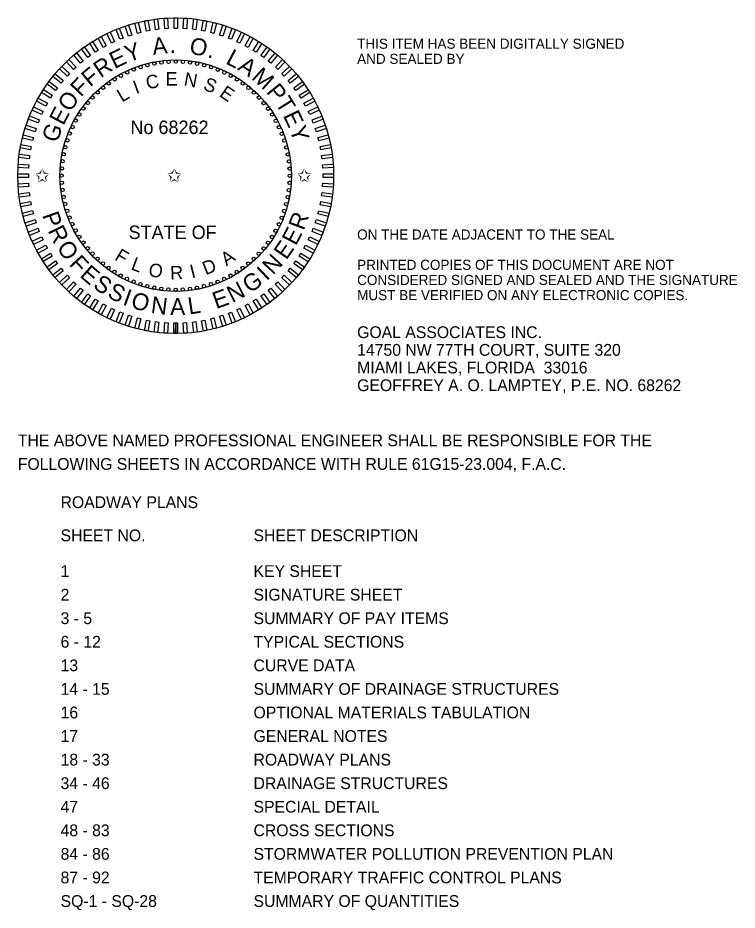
# Model space of a CAD drawing. Extents: x -811 to -790, y -2284 to -2178.
# Drawn here: x -810.41 to -806.14, y -2184.26 to -2178.96 of the extents above; entities that cross this region are included whole.
import ezdxf

# ---------------------------------------------------------------- set-up
doc = ezdxf.new("R2010")
doc.units = 0
for name, color, linetype in [('PlotBorder_dp', 7, 'Continuous'), ('TextMinor', 7, 'Continuous'), ('TextMisc', 7, 'Continuous'), ('TextShtNo', 7, 'Continuous')]:
    doc.layers.add(name, color=color, linetype=linetype)

msp = doc.modelspace()

# ---------------------------------------------------------------- linework, layer by layer
at = {"layer": 'TextMinor'}
for radius in [0.9375, 0.6875]:
    msp.add_circle((-809.477, -2179.9009), radius, dxfattribs=at)
at = {"layer": 'TextShtNo'}
for p, q in [((-809.487, -2180.8384), (-809.4871, -2180.7759)), ((-809.477, -2180.8384), (-809.4771, -2180.7759)), ((-809.467, -2180.8383), (-809.4671, -2180.7758))]:
    msp.add_line(p, q, dxfattribs=at)
for points in [[(-809.6309, -2179.0394), (-809.6507, -2179.0432), (-809.6624, -2178.9819), (-809.6426, -2178.9781)], [(-809.5765, -2179.0315), (-809.5965, -2179.034), (-809.6044, -2178.972), (-809.5843, -2178.9695)], [(-809.5217, -2179.0269), (-809.5419, -2179.0282), (-809.5458, -2178.9659), (-809.5256, -2178.9646)], [(-809.4668, -2179.0258), (-809.487, -2179.0258), (-809.487, -2178.9634), (-809.4668, -2178.9634)], [(-809.4118, -2179.0282), (-809.432, -2179.0269), (-809.4281, -2178.9646), (-809.4079, -2178.9659)], [(-809.3572, -2179.034), (-809.3772, -2179.0315), (-809.3694, -2178.9695), (-809.3493, -2178.9721)], [(-809.303, -2179.0432), (-809.3228, -2179.0395), (-809.3111, -2178.9781), (-809.2913, -2178.9819)], [(-809.7896, -2179.0835), (-809.8084, -2179.091), (-809.8314, -2179.0329), (-809.8126, -2179.0255)], [(-809.7377, -2179.0655), (-809.7569, -2179.0718), (-809.7762, -2179.0124), (-809.757, -2179.0061)], [(-809.6847, -2179.0508), (-809.7042, -2179.0558), (-809.7198, -2178.9953), (-809.7002, -2178.9903)], [(-809.2495, -2179.0559), (-809.269, -2179.0508), (-809.2535, -2178.9904), (-809.2339, -2178.9954)], [(-809.1969, -2179.0718), (-809.2161, -2179.0656), (-809.1968, -2179.0062), (-809.1776, -2179.0124)], [(-809.1454, -2179.091), (-809.1641, -2179.0836), (-809.1411, -2179.0256), (-809.1224, -2179.033)], [(-809.8896, -2179.1292), (-809.9073, -2179.1389), (-809.9373, -2179.0842), (-809.9197, -2179.0745)], [(-809.8403, -2179.1048), (-809.8586, -2179.1134), (-809.8852, -2179.0569), (-809.8669, -2179.0483)], [(-809.0952, -2179.1135), (-809.1134, -2179.1049), (-809.0868, -2179.0484), (-809.0686, -2179.057)], [(-809.0465, -2179.139), (-809.0642, -2179.1293), (-809.0341, -2179.0745), (-809.0164, -2179.0843)], [(-809.983, -2179.187), (-809.9994, -2179.1988), (-810.0361, -2179.1483), (-810.0197, -2179.1365)], [(-809.9372, -2179.1566), (-809.9543, -2179.1674), (-809.9877, -2179.1147), (-809.9707, -2179.1039)], [(-808.9995, -2179.1675), (-809.0165, -2179.1567), (-808.9831, -2179.104), (-808.966, -2179.1148)], [(-808.9544, -2179.1989), (-808.9707, -2179.1871), (-808.934, -2179.1366), (-808.9177, -2179.1484)], [(-810.0269, -2179.2202), (-810.0424, -2179.233), (-810.0822, -2179.1849), (-810.0667, -2179.172)], [(-808.9113, -2179.2331), (-808.9269, -2179.2203), (-808.8871, -2179.1722), (-808.8715, -2179.185)], [(-810.0685, -2179.256), (-810.0832, -2179.2698), (-810.126, -2179.2243), (-810.1113, -2179.2105)], [(-808.8705, -2179.27), (-808.8852, -2179.2562), (-808.8425, -2179.2106), (-808.8278, -2179.2245)], [(-810.1447, -2179.3353), (-810.1575, -2179.3508), (-810.2057, -2179.311), (-810.1928, -2179.2955)], [(-810.1078, -2179.2944), (-810.1217, -2179.3092), (-810.1672, -2179.2664), (-810.1534, -2179.2517)], [(-808.8321, -2179.3093), (-808.8459, -2179.2946), (-808.8004, -2179.2518), (-808.7866, -2179.2666)], [(-808.7962, -2179.351), (-808.8091, -2179.3354), (-808.761, -2179.2956), (-808.7481, -2179.3112)], [(-810.1789, -2179.3783), (-810.1907, -2179.3946), (-810.2413, -2179.3579), (-810.2294, -2179.3416)], [(-808.763, -2179.3948), (-808.7749, -2179.3784), (-808.7244, -2179.3417), (-808.7125, -2179.3581)], [(-810.2103, -2179.4234), (-810.2211, -2179.4404), (-810.2738, -2179.407), (-810.263, -2179.3899)], [(-808.7327, -2179.4406), (-808.7435, -2179.4236), (-808.6908, -2179.3901), (-808.68, -2179.4071)], [(-810.2388, -2179.4704), (-810.2486, -2179.4881), (-810.3033, -2179.458), (-810.2936, -2179.4403)], [(-808.7052, -2179.4882), (-808.715, -2179.4706), (-808.6603, -2179.4405), (-808.6505, -2179.4582)], [(-810.2644, -2179.5191), (-810.273, -2179.5373), (-810.3295, -2179.5108), (-810.3209, -2179.4925)], [(-808.6809, -2179.5375), (-808.6895, -2179.5193), (-808.633, -2179.4927), (-808.6244, -2179.5109)], [(-810.2868, -2179.5693), (-810.2942, -2179.588), (-810.3523, -2179.5651), (-810.3448, -2179.5463)], [(-808.6596, -2179.5882), (-808.667, -2179.5695), (-808.609, -2179.5465), (-808.6016, -2179.5652)], [(-810.306, -2179.6208), (-810.3122, -2179.64), (-810.3716, -2179.6207), (-810.3654, -2179.6015)], [(-808.6416, -2179.6402), (-808.6478, -2179.621), (-808.5885, -2179.6017), (-808.5822, -2179.6209)], [(-810.322, -2179.6734), (-810.327, -2179.6929), (-810.3875, -2179.6774), (-810.3824, -2179.6579)], [(-808.6269, -2179.6931), (-808.6319, -2179.6736), (-808.5714, -2179.658), (-808.5664, -2179.6776)], [(-810.3346, -2179.7269), (-810.3384, -2179.7467), (-810.3997, -2179.735), (-810.3959, -2179.7152)], [(-808.6155, -2179.7469), (-808.6193, -2179.7271), (-808.558, -2179.7154), (-808.5542, -2179.7352)], [(-810.3438, -2179.7811), (-810.3463, -2179.8011), (-810.4083, -2179.7933), (-810.4058, -2179.7733)], [(-808.6075, -2179.8013), (-808.6101, -2179.7813), (-808.5481, -2179.7735), (-808.5456, -2179.7935)], [(-810.3496, -2179.8358), (-810.3509, -2179.8559), (-810.4132, -2179.852), (-810.4119, -2179.8318)], [(-808.603, -2179.8561), (-808.6043, -2179.8359), (-808.542, -2179.832), (-808.5407, -2179.8522)], [(-810.352, -2179.8907), (-810.352, -2179.9109), (-810.4144, -2179.9109), (-810.4144, -2179.8907)], [(-808.6019, -2179.9111), (-808.6019, -2179.8909), (-808.5395, -2179.8909), (-808.5395, -2179.9111)], [(-810.3509, -2179.9456), (-810.3496, -2179.9658), (-810.4119, -2179.9697), (-810.4132, -2179.9496)], [(-808.6043, -2179.966), (-808.603, -2179.9458), (-808.5407, -2179.9498), (-808.542, -2179.9699)], [(-810.3464, -2180.0004), (-810.3438, -2180.0205), (-810.4058, -2180.0283), (-810.4083, -2180.0083)], [(-808.6101, -2180.0206), (-808.6076, -2180.0006), (-808.5456, -2180.0084), (-808.5481, -2180.0285)], [(-810.3384, -2180.0548), (-810.3346, -2180.0747), (-810.3959, -2180.0864), (-810.3997, -2180.0665)], [(-808.6193, -2180.0748), (-808.6155, -2180.055), (-808.5542, -2180.0667), (-808.558, -2180.0865)], [(-810.327, -2180.1086), (-810.322, -2180.1282), (-810.3825, -2180.1437), (-810.3875, -2180.1241)], [(-808.6319, -2180.1283), (-808.6269, -2180.1088), (-808.5664, -2180.1243), (-808.5715, -2180.1439)], [(-810.3123, -2180.1616), (-810.3061, -2180.1808), (-810.3654, -2180.2001), (-810.3717, -2180.1809)], [(-808.6479, -2180.181), (-808.6417, -2180.1618), (-808.5823, -2180.1811), (-808.5885, -2180.2003)], [(-810.2943, -2180.2135), (-810.2869, -2180.2323), (-810.3449, -2180.2553), (-810.3523, -2180.2365)], [(-808.6671, -2180.2325), (-808.6597, -2180.2137), (-808.6016, -2180.2367), (-808.6091, -2180.2554)], [(-810.273, -2180.2642), (-810.2644, -2180.2825), (-810.3209, -2180.3091), (-810.3295, -2180.2908)], [(-808.6895, -2180.2827), (-808.6809, -2180.2644), (-808.6244, -2180.291), (-808.633, -2180.3092)], [(-810.2487, -2180.3135), (-810.2389, -2180.3312), (-810.2936, -2180.3613), (-810.3034, -2180.3436)], [(-810.2212, -2180.3611), (-810.2104, -2180.3782), (-810.2631, -2180.4116), (-810.2739, -2180.3946)], [(-808.7436, -2180.3783), (-808.7328, -2180.3613), (-808.6801, -2180.3947), (-808.6909, -2180.4118)], [(-808.7151, -2180.3313), (-808.7053, -2180.3137), (-808.6506, -2180.3437), (-808.6603, -2180.3614)], [(-810.1909, -2180.407), (-810.179, -2180.4233), (-810.2295, -2180.46), (-810.2414, -2180.4437)], [(-808.775, -2180.4234), (-808.7632, -2180.4071), (-808.7126, -2180.4438), (-808.7245, -2180.4601)], [(-810.1577, -2180.4508), (-810.1448, -2180.4663), (-810.1929, -2180.5061), (-810.2058, -2180.4906)], [(-808.8092, -2180.4665), (-808.7964, -2180.4509), (-808.7482, -2180.4907), (-808.7611, -2180.5063)], [(-810.1218, -2180.4924), (-810.108, -2180.5072), (-810.1535, -2180.5499), (-810.1673, -2180.5352)], [(-808.8461, -2180.5073), (-808.8322, -2180.4926), (-808.7867, -2180.5353), (-808.8005, -2180.55)], [(-810.0834, -2180.5318), (-810.0687, -2180.5456), (-810.1114, -2180.5911), (-810.1261, -2180.5773)], [(-810.0426, -2180.5686), (-810.027, -2180.5815), (-810.0668, -2180.6296), (-810.0824, -2180.6167)], [(-808.927, -2180.5816), (-808.9115, -2180.5687), (-808.8717, -2180.6168), (-808.8872, -2180.6297)], [(-808.8854, -2180.5457), (-808.8707, -2180.5319), (-808.8279, -2180.5774), (-808.8426, -2180.5912)], [(-809.9995, -2180.6028), (-809.9832, -2180.6147), (-810.0199, -2180.6652), (-810.0362, -2180.6533)], [(-808.9709, -2180.6148), (-808.9545, -2180.6029), (-808.9178, -2180.6534), (-808.9342, -2180.6653)], [(-809.9544, -2180.6342), (-809.9374, -2180.645), (-809.9708, -2180.6978), (-809.9879, -2180.6869)], [(-809.9074, -2180.6628), (-809.8897, -2180.6725), (-809.9198, -2180.7272), (-809.9375, -2180.7175)], [(-809.0643, -2180.6726), (-809.0466, -2180.6628), (-809.0166, -2180.7176), (-809.0342, -2180.7273)], [(-809.0167, -2180.6451), (-808.9996, -2180.6343), (-808.9662, -2180.687), (-808.9832, -2180.6979)], [(-809.8587, -2180.6883), (-809.8405, -2180.6969), (-809.8671, -2180.7534), (-809.8853, -2180.7448)], [(-809.8085, -2180.7107), (-809.7898, -2180.7181), (-809.8128, -2180.7762), (-809.8315, -2180.7688)], [(-809.757, -2180.7299), (-809.7378, -2180.7362), (-809.7571, -2180.7955), (-809.7763, -2180.7893)], [(-809.2162, -2180.7362), (-809.197, -2180.73), (-809.1777, -2180.7894), (-809.1969, -2180.7956)], [(-809.1643, -2180.7182), (-809.1455, -2180.7108), (-809.1225, -2180.7688), (-809.1413, -2180.7763)], [(-809.1136, -2180.697), (-809.0953, -2180.6884), (-809.0687, -2180.7449), (-809.087, -2180.7535)], [(-809.7044, -2180.7459), (-809.6849, -2180.7509), (-809.7004, -2180.8114), (-809.72, -2180.8064)], [(-809.6509, -2180.7585), (-809.6311, -2180.7623), (-809.6428, -2180.8236), (-809.6626, -2180.8198)], [(-809.5967, -2180.7677), (-809.5767, -2180.7703), (-809.5845, -2180.8322), (-809.6046, -2180.8297)], [(-809.5421, -2180.7735), (-809.5219, -2180.7748), (-809.5258, -2180.8371), (-809.546, -2180.8358)], [(-809.4871, -2180.7759), (-809.467, -2180.7759), (-809.467, -2180.8383), (-809.4871, -2180.8383)], [(-809.4322, -2180.7748), (-809.412, -2180.7735), (-809.4081, -2180.8359), (-809.4283, -2180.8371)], [(-809.3774, -2180.7703), (-809.3574, -2180.7677), (-809.3495, -2180.8297), (-809.3696, -2180.8322)], [(-809.323, -2180.7623), (-809.3032, -2180.7585), (-809.2915, -2180.8199), (-809.3113, -2180.8236)], [(-809.2692, -2180.7509), (-809.2497, -2180.7459), (-809.2341, -2180.8064), (-809.2537, -2180.8114)]]:
    msp.add_lwpolyline(points, close=True, dxfattribs=at)
for centre in [(-809.6858, -2179.2564), (-809.6449, -2179.2445), (-809.6033, -2179.2353), (-809.5613, -2179.2287), (-809.5189, -2179.2247), (-809.4764, -2179.2234), (-809.4338, -2179.2248), (-809.3915, -2179.2288), (-809.3495, -2179.2355), (-809.3079, -2179.2448), (-809.2671, -2179.2567), (-809.8028, -2179.3069), (-809.7649, -2179.2876), (-809.7258, -2179.2708), (-809.227, -2179.2712), (-809.188, -2179.2881), (-809.1501, -2179.3075), (-809.8747, -2179.3525), (-809.8395, -2179.3286), (-809.1135, -2179.3292), (-809.0783, -2179.3531), (-809.9403, -2179.4066), (-809.9084, -2179.3785), (-809.0447, -2179.3792), (-809.0128, -2179.4074), (-809.9986, -2179.4686), (-809.9704, -2179.4367), (-808.9827, -2179.4375), (-808.9546, -2179.4695), (-810.0247, -2179.5022), (-808.9285, -2179.5031), (-810.0703, -2179.574), (-810.0487, -2179.5374), (-808.9046, -2179.5383), (-808.883, -2179.575), (-810.0897, -2179.6119), (-808.8637, -2179.6129), (-810.1066, -2179.651), (-808.8468, -2179.652), (-810.133, -2179.7318), (-810.1211, -2179.691), (-808.8325, -2179.6921), (-808.8206, -2179.7329), (-810.1423, -2179.7734), (-808.8114, -2179.7745), (-810.149, -2179.8154), (-808.8048, -2179.8165), (-810.153, -2179.8578), (-808.8008, -2179.8589), (-810.1544, -2179.9003), (-810.1531, -2179.9428), (-808.8009, -2179.944), (-808.7995, -2179.9014), (-810.1491, -2179.9852), (-808.8049, -2179.9863), (-810.1425, -2180.0273), (-808.8116, -2180.0284), (-810.1333, -2180.0688), (-810.1214, -2180.1097), (-808.8209, -2180.0699), (-810.1071, -2180.1497), (-808.8473, -2180.1508), (-808.8328, -2180.1108), (-810.0902, -2180.1888), (-808.8642, -2180.1898), (-810.0709, -2180.2267), (-810.0493, -2180.2634), (-808.9052, -2180.2644), (-808.8836, -2180.2277), (-810.0254, -2180.2986), (-808.9292, -2180.2995), (-809.9993, -2180.3323), (-809.9712, -2180.3642), (-808.9835, -2180.365), (-808.9553, -2180.3331), (-809.9411, -2180.3943), (-809.9092, -2180.4225), (-809.0456, -2180.4232), (-809.0136, -2180.3951), (-809.8756, -2180.4486), (-809.8404, -2180.4726), (-809.1144, -2180.4732), (-809.0792, -2180.4493), (-809.8038, -2180.4943), (-809.7659, -2180.5136), (-809.7269, -2180.5306), (-809.2281, -2180.531), (-809.189, -2180.5141), (-809.1511, -2180.4948), (-809.6868, -2180.545), (-809.646, -2180.5569), (-809.6044, -2180.5662), (-809.5624, -2180.5729), (-809.5201, -2180.577), (-809.477, -2180.5784), (-809.435, -2180.577), (-809.3926, -2180.5731), (-809.3506, -2180.5664), (-809.309, -2180.5572), (-809.2681, -2180.5454)]:
    msp.add_circle(centre, 0.01, dxfattribs=at)

# ---------------------------------------------------------------- texts
at = {"layer": 'PlotBorder_dp'}
for s, height, p in [('THIS ITEM HAS BEEN DIGITALLY SIGNED ', 0.06, (-808.3993, -2179.147)), ('AND SEALED BY', 0.06, (-808.3993, -2179.237)), ('ON THE DATE ADJACENT TO THE SEAL', 0.06, (-808.3993, -2180.2804)), ('PRINTED COPIES OF THIS DOCUMENT ARE NOT ', 0.06, (-808.3993, -2180.4604)), ('CONSIDERED SIGNED AND SEALED AND THE SIGNATURE ', 0.06, (-808.3993, -2180.5504)), ('MUST BE VERIFIED ON ANY ELECTRONIC COPIES.', 0.06, (-808.3993, -2180.6404)), ('GOAL ASSOCIATES INC.', 0.07, (-808.3993, -2180.8657)), ('14750 NW 77TH COURT, SUITE 320', 0.07, (-808.3993, -2180.9707)), ('MIAMI LAKES, FLORIDA  33016', 0.07, (-808.3993, -2181.0757)), ('GEOFFREY A. O. LAMPTEY, P.E. NO. 68262', 0.07, (-808.3993, -2181.1807)), ('THE ABOVE NAMED PROFESSIONAL ENGINEER SHALL BE RESPONSIBLE FOR THE ', 0.07, (-810.4145, -2181.5084)), ('FOLLOWING SHEETS IN ACCORDANCE WITH RULE 61G15-23.004, F.A.C.', 0.07, (-810.4145, -2181.6484)), ('ROADWAY PLANS', 0.07, (-810.1607, -2181.8755))]:
    msp.add_text(s, height=height, dxfattribs=at).set_placement(p)
at = {"layer": 'TextMisc'}
for s, p in [('SHEET NO.', (-810.1607, -2182.0725)), ('SHEET DESCRIPTION', (-809.0148, -2182.0725)), ('1', (-810.1607, -2182.2847)), ('KEY SHEET', (-809.0148, -2182.2847)), ('2', (-810.1607, -2182.4247)), ('SIGNATURE SHEET', (-809.0148, -2182.4247)), ('3 - 5', (-810.1607, -2182.5647)), ('SUMMARY OF PAY ITEMS', (-809.0148, -2182.5647)), ('6 - 12', (-810.1607, -2182.7047)), ('TYPICAL SECTIONS', (-809.0148, -2182.7047)), ('13', (-810.1607, -2182.8447)), ('CURVE DATA', (-809.0148, -2182.8447)), ('14 - 15', (-810.1607, -2182.9847)), ('SUMMARY OF DRAINAGE STRUCTURES', (-809.0148, -2182.9847)), ('16', (-810.1607, -2183.1247)), ('OPTIONAL MATERIALS TABULATION', (-809.0148, -2183.1247)), ('17', (-810.1607, -2183.2647)), ('GENERAL NOTES', (-809.0148, -2183.2647)), ('18 - 33', (-810.1607, -2183.4047)), ('ROADWAY PLANS', (-809.0148, -2183.4047)), ('34 - 46', (-810.1607, -2183.5447)), ('DRAINAGE STRUCTURES', (-809.0148, -2183.5447)), ('47', (-810.1607, -2183.6847)), ('SPECIAL DETAIL', (-809.0148, -2183.6847)), ('48 - 83', (-810.1607, -2183.8247)), ('CROSS SECTIONS', (-809.0148, -2183.8247)), ('84 - 86', (-810.1607, -2183.9647)), ('STORMWATER POLLUTION PREVENTION PLAN', (-809.0148, -2183.9647)), ('87 - 92', (-810.1607, -2184.1047)), ('TEMPORARY TRAFFIC CONTROL PLANS', (-809.0148, -2184.1047)), ('SQ-1 - SQ-28', (-810.1607, -2184.2447)), ('SUMMARY OF QUANTITIES', (-809.0148, -2184.2447))]:
    msp.add_text(s, height=0.07, dxfattribs=at).set_placement(p)
at = {"layer": 'TextShtNo'}
for s, height, rotation, p in [('A', 0.1, 6.3024, (-809.6107, -2179.1837)), ('O', 0.1, 349.6813, (-809.3999, -2179.1754)), ('E', 0.1, 25.5991, (-809.8401, -2179.2682)), ('Y', 0.1, 18.5568, (-809.7598, -2179.2284)), ('.', 0.1, 358.5354, (-809.5125, -2179.1722)), ('.', 0.1, 341.0204, (-809.2916, -2179.1953)), ('L', 0.1, 332.1663, (-809.1852, -2179.2322)), ('F', 0.1, 39.8708, (-809.9849, -2179.3773)), ('R', 0.1, 33.4204, (-809.9229, -2179.3235)), ('A', 0.1, 325.9031, (-809.114, -2179.2681)), ('C', 0.08, 12.2025, (-809.6447, -2179.3893)), ('E', 0.08, 0.4186, (-809.5367, -2179.3658)), ('N', 0.08, 349.2914, (-809.4323, -2179.3643)), ('M', 0.1, 318.1361, (-809.0318, -2179.3229)), ('F', 0.1, 46.3211, (-810.0405, -2179.4376)), ('I', 0.08, 20.0117, (-809.7126, -2179.4168)), ('S', 0.08, 337.0221, (-809.3193, -2179.3861)), ('P', 0.1, 308.6901, (-808.943, -2179.4038)), ('O', 0.1, 54.982, (-810.1038, -2179.5278)), ('L', 0.08, 30.4021, (-809.7961, -2179.4672)), ('E', 0.08, 325.8663, (-809.2227, -2179.4263)), ('T', 0.1, 301.9499, (-808.8883, -2179.4699)), ('E', 0.1, 62.0242, (-810.1449, -2179.6074)), ('E', 0.1, 295.1251, (-808.8413, -2179.5429)), ('G', 0.1, 70.5583, (-810.181, -2179.7098)), ('Y', 0.1, 288.0828, (-808.8022, -2179.6236)), ('P', 0.1, 289.4055, (-810.2717, -2180.1354)), ('R', 0.1, 69.5134, (-808.7168, -2180.2306)), ('R', 0.1, 296.1458, (-810.2386, -2180.2271)), ('E', 0.1, 62.4712, (-808.7629, -2180.3213)), ('O', 0.1, 303.9671, (-810.1872, -2180.3277)), ('E', 0.1, 55.4289, (-808.8198, -2180.4057)), ('F', 0.08, 328.7241, (-809.845, -2180.3975)), ('A', 0.08, 34.4992, (-809.1751, -2180.4403)), ('N', 0.1, 47.1788, (-808.8991, -2180.4947)), ('F', 0.1, 312.628, (-810.1148, -2180.4298)), ('L', 0.08, 339.2916, (-809.7477, -2180.4565)), ('D', 0.08, 22.0128, (-809.2989, -2180.4928)), ('E', 0.1, 319.0783, (-810.0513, -2180.4981)), ('O', 0.08, 349.6821, (-809.643, -2180.4962)), ('R', 0.08, 2.3398, (-809.5085, -2180.5182)), ('I', 0.08, 14.2037, (-809.381, -2180.5115)), ('I', 0.1, 43.6456, (-808.9368, -2180.5292)), ('S', 0.1, 326.1206, (-809.9738, -2180.564)), ('G', 0.1, 35.1115, (-809.036, -2180.6024)), ('S', 0.1, 333.193, (-809.8883, -2180.6201)), ('I', 0.1, 340.2654, (-809.7966, -2180.6653)), ('E', 0.1, 19.8191, (-809.2366, -2180.6939)), ('N', 0.1, 26.8614, (-809.1412, -2180.6584)), ('O', 0.1, 343.7986, (-809.7489, -2180.6836)), ('N', 0.1, 352.4595, (-809.628, -2180.7156)), ('A', 0.1, 0.7097, (-809.5095, -2180.7288)), ('L', 0.1, 8.4767, (-809.3973, -2180.7256))]:
    msp.add_text(s, height=height, rotation=rotation, dxfattribs=at).set_placement(p)
for s, p in [('No 68262', (-809.7459, -2179.6536)), ('✩', (-810.3119, -2179.9388)), ('✩', (-809.5272, -2179.9388)), ('✩', (-808.7554, -2179.9388)), ('STATE OF', (-809.7567, -2180.2771))]:
    msp.add_text(s, height=0.08, dxfattribs=at).set_placement(p)

doc.saveas('drawing.dxf')
